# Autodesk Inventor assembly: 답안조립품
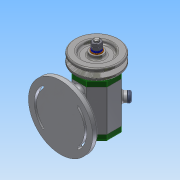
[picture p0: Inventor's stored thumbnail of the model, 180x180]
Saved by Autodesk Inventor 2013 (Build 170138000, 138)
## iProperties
Created: 2017-06
Part Number: 답안조립품
Document SubType Name: Assembly
Designer: Administrator
Author: Administrator
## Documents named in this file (14)
- C:\Users\Administrator\Desktop\470608V1016\답안조립품.iam
- C:\Users\Administrator\Desktop\470608V1016\본체.ipt
- C:\Users\Administrator\Desktop\470608V1016\V벨트풀리.ipt
- C:\Users\Administrator\Desktop\470608V1016\고무캡.ipt
- C:\Users\Administrator\Desktop\470608V1016\너트 M 8.ipt
- C:\Users\Administrator\Desktop\470608V1016\뒤커버.ipt
- C:\Users\Administrator\Desktop\470608V1016\베어링 15 x 32 x 9.ipt
- C:\Users\Administrator\Desktop\470608V1016\볼트 M4 x 12.ipt
- C:\Users\Administrator\Desktop\470608V1016\스프링와셔 8.ipt
- C:\Users\Administrator\Desktop\470608V1016\앞커버.ipt
- C:\Users\Administrator\Desktop\470608V1016\오일 실 15 25 7.ipt
- C:\Users\Administrator\Desktop\470608V1016\와셔 8x17.ipt
- C:\Users\Administrator\Desktop\470608V1016\축.ipt
- C:\Users\Administrator\Desktop\470608V1016\키 3 x 3 x 12.ipt
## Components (2 placed, 2 different names)
1. V벨트풀리:1
2. 고무캡:1
